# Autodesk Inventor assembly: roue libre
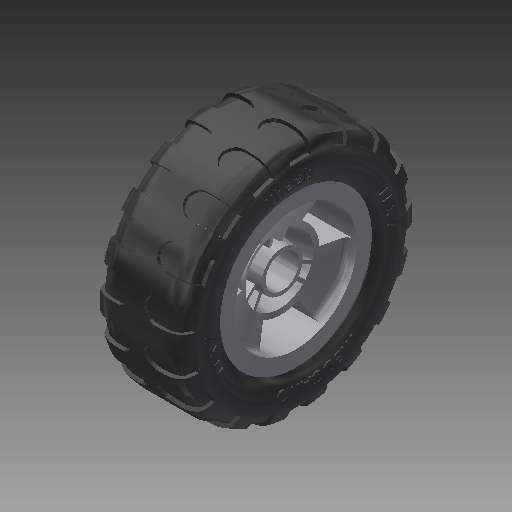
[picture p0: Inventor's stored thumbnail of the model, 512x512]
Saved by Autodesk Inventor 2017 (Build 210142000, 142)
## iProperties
Part Number: roue libre
Material: Générique
Document SubType Name: Assembly
Designer: ficho
Author: ficho
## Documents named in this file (3)
- G:\travail\année 2017-2018\1STI2D\challenge\roue libre.iam
- G:\travail\année 2017-2018\1STI2D\challenge\pièces meccano step\A045 - MECCANO JUNIOR.ipt
- G:\travail\année 2017-2018\1STI2D\challenge\pièces meccano step\A046 - MECCANO JUNIOR.ipt
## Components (2 placed, 2 different names)
1. A045 - MECCANO JUNIOR:1 — Logement:1
2. A046 - MECCANO JUNIOR:1 — Logement:1
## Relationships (1: Insert 1)
- Logement:1 [Insert]: A045 - MECCANO JUNIOR:1 ↔ A046 - MECCANO JUNIOR:1
